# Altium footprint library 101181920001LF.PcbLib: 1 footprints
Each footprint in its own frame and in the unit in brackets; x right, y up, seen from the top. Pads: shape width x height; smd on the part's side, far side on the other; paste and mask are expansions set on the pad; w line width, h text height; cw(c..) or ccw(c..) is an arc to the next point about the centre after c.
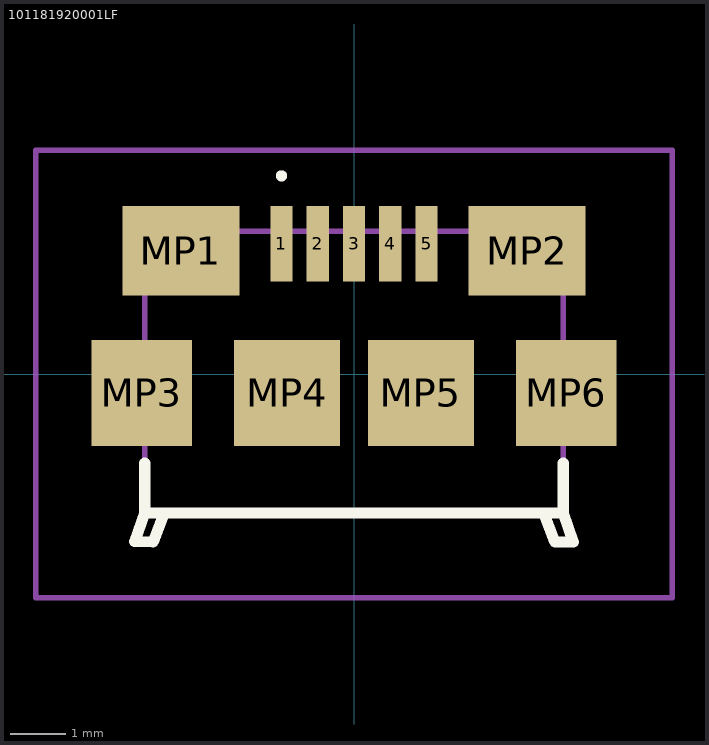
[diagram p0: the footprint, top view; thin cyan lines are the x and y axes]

## 101181920001LF [mm]
pads (11):
  rect 0.4x1.35 smd: 1(-1.3,2.335) 2(-0.65,2.335) 3(0,2.335) 4(0.65,2.335) 5(1.3,2.335)
  rect 2.1x1.6 smd: MP1(-3.1,2.21) MP2(3.1,2.21)
  rect 1.8x1.9 smd: MP3(-3.8,-0.34) MP6(3.8,-0.34)
  rect 1.9x1.9 smd: MP4(-1.2,-0.34) MP5(1.2,-0.34)
Top Overlay:
  lines w0.1: -1.3,3.5 cw(c-1.3,3.55) -1.3,3.6 ; -1.3,3.5 -1.3,3.5 ; -1.3,3.5 ccw(c-1.3,3.55) -1.3,3.6 ; -1.3,3.6 -1.3,3.6
  lines w0.2: -3.75,-1.6 -3.75,-2.49 ; -3.4,-2.49 -3.6,-3.01 -3.93,-3 -3.75,-2.49 ; 3.4,-2.49 3.6,-3.01 3.93,-3.01 3.75,-2.49 ; 3.75,-1.6 3.75,-2.49 ; -3.75,-2.49 3.75,-2.49
Mechanical 15:
  lines w0.1: -3.4,-2.49 -3.6,-3.01 -3.93,-3.01 -3.75,-2.49 ; 3.4,-2.49 3.6,-3.01 3.93,-3.01 3.75,-2.49 ; -3.75,-2.49 3.75,-2.49 ; -3.75,-2.49 -3.75,2.56 3.75,2.56 3.75,-2.49
Mechanical 20:
  lines w0.1: -5.7,-4.01 5.7,-4.01 5.7,4.01 -5.7,4.01 -5.7,-4.01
